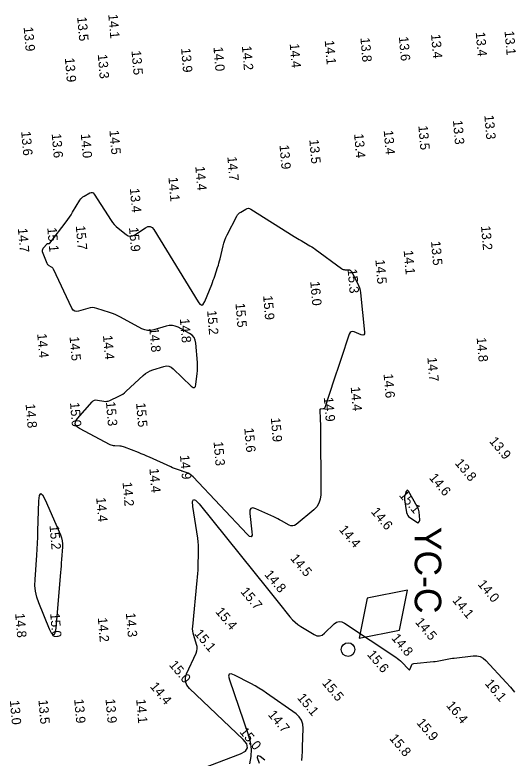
# Model space of a CAD drawing. Extents: x 988130 to 1132882, y 654656 to 841453.
# Drawn here: x 1101312.3 to 1101574.5, y 687754.5 to 688147.1 of the extents above; entities that cross this region are included whole.
import ezdxf

# ---------------------------------------------------------------- set-up
doc = ezdxf.new("R2010")
doc.units = 0
for name, color, linetype in [('V-CHAN-NAID', 7, 'Continuous'), ('V-TOPO-MAJR', 7, 'Continuous'), ('V-TOPO-SOUN', 7, 'Continuous')]:
    doc.layers.add(name, color=color, linetype=linetype)

msp = doc.modelspace()

# ---------------------------------------------------------------- linework, layer by layer
at = {"layer": 'V-CHAN-NAID'}
msp.add_lwpolyline([(1101494.3, 687817.8), (1101515.51, 687822.04), (1101519.76, 687843.26), (1101498.54, 687839.01)], close=True, dxfattribs=at)
msp.add_lwpolyline([(1101494.3, 687817.8), (1101515.51, 687822.04), (1101519.76, 687843.26), (1101498.54, 687839.01)], close=True, dxfattribs=at)
msp.add_circle((1101488.36, 687811.86), 3.6, dxfattribs=at)
msp.add_circle((1101488.36, 687811.86), 3.6, dxfattribs=at)
at = {"layer": 'V-TOPO-MAJR'}
for points in [[(1101489.55, 688012.21), (1101489.88, 688011.94), (1101490.14, 688011.56), (1101493.4, 688005.35), (1101493.96, 688004.15), (1101494.4, 688002.92), (1101494.72, 688001.65), (1101494.92, 688000.34), (1101497.07, 687979.46), (1101497.05, 687978.62), (1101496.76, 687978.13), (1101496.2, 687977.98), (1101495.38, 687978.18), (1101491.59, 687979.67), (1101490.71, 687979.88), (1101490, 687979.75), (1101489.44, 687979.28), (1101489.04, 687978.48), (1101484.5, 687964.99), (1101483.63, 687962.42), (1101482.77, 687959.84), (1101481.92, 687957.27), (1101481.07, 687954.69), (1101476.09, 687939.59), (1101475.96, 687939.32), (1101475.78, 687939.13), (1101475.54, 687939), (1101475.25, 687938.94), (1101473.97, 687938.84), (1101473.7, 687938.78), (1101473.5, 687938.64), (1101473.4, 687938.43), (1101473.38, 687938.15), (1101473.64, 687933.95), (1101473.69, 687933.14), (1101473.72, 687932.34), (1101473.74, 687931.53), (1101473.75, 687930.72), (1101473.91, 687893.52), (1101473.69, 687891.23), (1101473, 687889.16), (1101471.85, 687887.31), (1101470.24, 687885.68), (1101460.96, 687877.98), (1101460.06, 687877.42), (1101459.14, 687877.17), (1101458.18, 687877.25), (1101457.2, 687877.65), (1101453.21, 687879.91), (1101452.21, 687880.46), (1101451.19, 687880.99), (1101450.17, 687881.49), (1101449.13, 687881.97), (1101439.7, 687886.15), (1101438.05, 687886.64), (1101436.95, 687886.39), (1101436.4, 687885.41), (1101436.39, 687883.69), (1101437.6, 687874.06), (1101437.66, 687872.26), (1101437.24, 687871.45), (1101436.35, 687871.65), (1101435, 687872.83), (1101406.5, 687903.06), (1101405.72, 687903.8), (1101404.86, 687904.43), (1101403.93, 687904.95), (1101402.92, 687905.35), (1101398.77, 687906.76), (1101397.74, 687907.12), (1101396.71, 687907.51), (1101395.7, 687907.92), (1101394.7, 687908.36), (1101383.38, 687913.46), (1101381.97, 687914.08), (1101380.56, 687914.69), (1101379.13, 687915.29), (1101377.71, 687915.87), (1101370.33, 687918.82), (1101369.71, 687919.03), (1101369.09, 687919.19), (1101368.45, 687919.3), (1101367.8, 687919.34), (1101365.17, 687919.43), (1101364.52, 687919.48), (1101363.89, 687919.61), (1101363.28, 687919.81), (1101362.69, 687920.08), (1101346.39, 687928.61), (1101344.85, 687929.72), (1101344.17, 687930.99), (1101344.35, 687932.41), (1101345.4, 687933.99), (1101353.12, 687942.69), (1101353.71, 687943.23), (1101354.38, 687943.57), (1101355.12, 687943.71), (1101355.92, 687943.65), (1101359.26, 687943.04), (1101360.09, 687942.95), (1101360.9, 687942.99), (1101361.7, 687943.15), (1101362.48, 687943.45), (1101367.3, 687945.69), (1101368.34, 687946.22), (1101369.32, 687946.82), (1101370.25, 687947.51), (1101371.14, 687948.26), (1101380.17, 687956.68), (1101381.31, 687957.63), (1101382.54, 687958.44), (1101383.85, 687959.1), (1101385.25, 687959.62), (1101391.01, 687961.39), (1101392.4, 687961.64), (1101393.71, 687961.53), (1101394.92, 687961.04), (1101396.05, 687960.18), (1101405.53, 687951.02), (1101406.47, 687950.32), (1101407.19, 687950.23), (1101407.69, 687950.75), (1101407.97, 687951.88), (1101408.66, 687957.65), (1101408.8, 687959.09), (1101408.86, 687960.54), (1101408.86, 687961.98), (1101408.78, 687963.43), (1101407.96, 687973.69), (1101407.65, 687975.3), (1101407, 687976.68), (1101406.01, 687977.84), (1101404.67, 687978.78), (1101398.63, 687982.09), (1101397.1, 687982.75), (1101395.54, 687983.08), (1101393.94, 687983.07), (1101392.31, 687982.73), (1101385.71, 687980.71), (1101384.08, 687980.37), (1101382.48, 687980.36), (1101380.92, 687980.68), (1101379.38, 687981.34), (1101368.19, 687987.4), (1101366.77, 687988.13), (1101365.33, 687988.79), (1101363.86, 687989.38), (1101362.35, 687989.9), (1101355.66, 687992.06), (1101354.46, 687992.35), (1101353.25, 687992.45), (1101352.05, 687992.37), (1101350.84, 687992.09), (1101346.01, 687990.62), (1101344.89, 687990.44), (1101343.93, 687990.63), (1101343.14, 687991.21), (1101342.51, 687992.16), (1101332.77, 688012.7), (1101332.58, 688013.03), (1101332.34, 688013.33), (1101332.07, 688013.59), (1101331.75, 688013.8), (1101330.39, 688014.6), (1101330.07, 688014.82), (1101329.81, 688015.08), (1101329.59, 688015.38), (1101329.42, 688015.72), (1101327, 688021.86), (1101326.86, 688022.38), (1101326.87, 688022.87), (1101327.02, 688023.34), (1101327.32, 688023.79), (1101329.37, 688026.18), (1101329.47, 688026.27), (1101329.57, 688026.33), (1101329.69, 688026.36), (1101329.82, 688026.36), (1101330.36, 688026.32), (1101330.48, 688026.33), (1101330.6, 688026.36), (1101330.7, 688026.42), (1101330.79, 688026.51), (1101339.44, 688037.81), (1101340.34, 688039.03), (1101341.21, 688040.27), (1101342.04, 688041.53), (1101342.84, 688042.82), (1101346.66, 688049.18), (1101347.13, 688049.86), (1101347.67, 688050.46), (1101348.29, 688050.99), (1101348.98, 688051.43), (1101351.9, 688053.07), (1101352.6, 688053.34), (1101353.22, 688053.33), (1101353.78, 688053.04), (1101354.26, 688052.48), (1101363.18, 688038.54), (1101363.97, 688037.41), (1101364.84, 688036.37), (1101365.8, 688035.4), (1101366.84, 688034.5), (1101371.16, 688031.08), (1101372.25, 688030.43), (1101373.36, 688030.17), (1101374.49, 688030.33), (1101375.63, 688030.88), (1101381.37, 688034.65), (1101382.64, 688035.25), (1101383.79, 688035.29), (1101384.82, 688034.76), (1101385.72, 688033.68), (1101409.09, 687995.48), (1101410.09, 687994.22), (1101411.03, 687993.84), (1101411.9, 687994.36), (1101412.69, 687995.77), (1101416.32, 688004.68), (1101416.76, 688005.79), (1101417.19, 688006.91), (1101417.59, 688008.04), (1101417.98, 688009.17), (1101419.48, 688013.71), (1101419.85, 688014.85), (1101420.18, 688016), (1101420.49, 688017.15), (1101420.77, 688018.31), (1101422.31, 688025.06), (1101422.7, 688026.56), (1101423.19, 688028.02), (1101423.77, 688029.45), (1101424.44, 688030.84), (1101429.61, 688040.79), (1101430.01, 688041.45), (1101430.49, 688042.03), (1101431.04, 688042.53), (1101431.68, 688042.96), (1101434.37, 688044.54), (1101435.04, 688044.83), (1101435.71, 688044.92), (1101436.38, 688044.81), (1101437.04, 688044.49), (1101459.83, 688030.11), (1101460.75, 688029.53), (1101461.68, 688028.96), (1101462.61, 688028.41), (1101463.55, 688027.86), (1101467.32, 688025.7), (1101468.26, 688025.15), (1101469.18, 688024.57), (1101470.08, 688023.97), (1101470.97, 688023.34), (1101484.98, 688013.12), (1101485.38, 688012.87), (1101485.82, 688012.68), (1101486.27, 688012.57), (1101486.75, 688012.52), (1101488.7, 688012.45), (1101489.16, 688012.39)], [(1101489.55, 688012.21), (1101489.88, 688011.94), (1101490.14, 688011.56), (1101493.4, 688005.35), (1101493.96, 688004.15), (1101494.4, 688002.92), (1101494.72, 688001.65), (1101494.92, 688000.34), (1101497.07, 687979.46), (1101497.05, 687978.62), (1101496.76, 687978.13), (1101496.2, 687977.98), (1101495.38, 687978.18), (1101491.59, 687979.67), (1101490.71, 687979.88), (1101490, 687979.75), (1101489.44, 687979.28), (1101489.04, 687978.48), (1101484.5, 687964.99), (1101483.63, 687962.42), (1101482.77, 687959.84), (1101481.92, 687957.27), (1101481.07, 687954.69), (1101476.09, 687939.59), (1101475.96, 687939.32), (1101475.78, 687939.13), (1101475.54, 687939), (1101475.25, 687938.94), (1101473.97, 687938.84), (1101473.7, 687938.78), (1101473.5, 687938.64), (1101473.4, 687938.43), (1101473.38, 687938.15), (1101473.64, 687933.95), (1101473.69, 687933.14), (1101473.72, 687932.34), (1101473.74, 687931.53), (1101473.75, 687930.72), (1101473.91, 687893.52), (1101473.69, 687891.23), (1101473, 687889.16), (1101471.85, 687887.31), (1101470.24, 687885.68), (1101460.96, 687877.98), (1101460.06, 687877.42), (1101459.14, 687877.17), (1101458.18, 687877.25), (1101457.2, 687877.65), (1101453.21, 687879.91), (1101452.21, 687880.46), (1101451.19, 687880.99), (1101450.17, 687881.49), (1101449.13, 687881.97), (1101439.7, 687886.15), (1101438.05, 687886.64), (1101436.95, 687886.39), (1101436.4, 687885.41), (1101436.39, 687883.69), (1101437.6, 687874.06), (1101437.66, 687872.26), (1101437.24, 687871.45), (1101436.35, 687871.65), (1101435, 687872.83), (1101406.5, 687903.06), (1101405.72, 687903.8), (1101404.86, 687904.43), (1101403.93, 687904.95), (1101402.92, 687905.35), (1101398.77, 687906.76), (1101397.74, 687907.12), (1101396.71, 687907.51), (1101395.7, 687907.92), (1101394.7, 687908.36), (1101383.38, 687913.46), (1101381.97, 687914.08), (1101380.56, 687914.69), (1101379.13, 687915.29), (1101377.71, 687915.87), (1101370.33, 687918.82), (1101369.71, 687919.03), (1101369.09, 687919.19), (1101368.45, 687919.3), (1101367.8, 687919.34), (1101365.17, 687919.43), (1101364.52, 687919.48), (1101363.89, 687919.61), (1101363.28, 687919.81), (1101362.69, 687920.08), (1101346.39, 687928.61), (1101344.85, 687929.72), (1101344.17, 687930.99), (1101344.35, 687932.41), (1101345.4, 687933.99), (1101353.12, 687942.69), (1101353.71, 687943.23), (1101354.38, 687943.57), (1101355.12, 687943.71), (1101355.92, 687943.65), (1101359.26, 687943.04), (1101360.09, 687942.95), (1101360.9, 687942.99), (1101361.7, 687943.15), (1101362.48, 687943.45), (1101367.3, 687945.69), (1101368.34, 687946.22), (1101369.32, 687946.82), (1101370.25, 687947.51), (1101371.14, 687948.26), (1101380.17, 687956.68), (1101381.31, 687957.63), (1101382.54, 687958.44), (1101383.85, 687959.1), (1101385.25, 687959.62), (1101391.01, 687961.39), (1101392.4, 687961.64), (1101393.71, 687961.53), (1101394.92, 687961.04), (1101396.05, 687960.18), (1101405.53, 687951.02), (1101406.47, 687950.32), (1101407.19, 687950.23), (1101407.69, 687950.75), (1101407.97, 687951.88), (1101408.66, 687957.65), (1101408.8, 687959.09), (1101408.86, 687960.54), (1101408.86, 687961.98), (1101408.78, 687963.43), (1101407.96, 687973.69), (1101407.65, 687975.3), (1101407, 687976.68), (1101406.01, 687977.84), (1101404.67, 687978.78), (1101398.63, 687982.09), (1101397.1, 687982.75), (1101395.54, 687983.08), (1101393.94, 687983.07), (1101392.31, 687982.73), (1101385.71, 687980.71), (1101384.08, 687980.37), (1101382.48, 687980.36), (1101380.92, 687980.68), (1101379.38, 687981.34), (1101368.19, 687987.4), (1101366.77, 687988.13), (1101365.33, 687988.79), (1101363.86, 687989.38), (1101362.35, 687989.9), (1101355.66, 687992.06), (1101354.46, 687992.35), (1101353.25, 687992.45), (1101352.05, 687992.37), (1101350.84, 687992.09), (1101346.01, 687990.62), (1101344.89, 687990.44), (1101343.93, 687990.63), (1101343.14, 687991.21), (1101342.51, 687992.16), (1101332.77, 688012.7), (1101332.58, 688013.03), (1101332.34, 688013.33), (1101332.07, 688013.59), (1101331.75, 688013.8), (1101330.39, 688014.6), (1101330.07, 688014.82), (1101329.81, 688015.08), (1101329.59, 688015.38), (1101329.42, 688015.72), (1101327, 688021.86), (1101326.86, 688022.38), (1101326.87, 688022.87), (1101327.02, 688023.34), (1101327.32, 688023.79), (1101329.37, 688026.18), (1101329.47, 688026.27), (1101329.57, 688026.33), (1101329.69, 688026.36), (1101329.82, 688026.36), (1101330.36, 688026.32), (1101330.48, 688026.33), (1101330.6, 688026.36), (1101330.7, 688026.42), (1101330.79, 688026.51), (1101339.44, 688037.81), (1101340.34, 688039.03), (1101341.21, 688040.27), (1101342.04, 688041.53), (1101342.84, 688042.82), (1101346.66, 688049.18), (1101347.13, 688049.86), (1101347.67, 688050.46), (1101348.29, 688050.99), (1101348.98, 688051.43), (1101351.9, 688053.07), (1101352.6, 688053.34), (1101353.22, 688053.33), (1101353.78, 688053.04), (1101354.26, 688052.48), (1101363.18, 688038.54), (1101363.97, 688037.41), (1101364.84, 688036.37), (1101365.8, 688035.4), (1101366.84, 688034.5), (1101371.16, 688031.08), (1101372.25, 688030.43), (1101373.36, 688030.17), (1101374.49, 688030.33), (1101375.63, 688030.88), (1101381.37, 688034.65), (1101382.64, 688035.25), (1101383.79, 688035.29), (1101384.82, 688034.76), (1101385.72, 688033.68), (1101409.09, 687995.48), (1101410.09, 687994.22), (1101411.03, 687993.84), (1101411.9, 687994.36), (1101412.69, 687995.77), (1101416.32, 688004.68), (1101416.76, 688005.79), (1101417.19, 688006.91), (1101417.59, 688008.04), (1101417.98, 688009.17), (1101419.48, 688013.71), (1101419.85, 688014.85), (1101420.18, 688016), (1101420.49, 688017.15), (1101420.77, 688018.31), (1101422.31, 688025.06), (1101422.7, 688026.56), (1101423.19, 688028.02), (1101423.77, 688029.45), (1101424.44, 688030.84), (1101429.61, 688040.79), (1101430.01, 688041.45), (1101430.49, 688042.03), (1101431.04, 688042.53), (1101431.68, 688042.96), (1101434.37, 688044.54), (1101435.04, 688044.83), (1101435.71, 688044.92), (1101436.38, 688044.81), (1101437.04, 688044.49), (1101459.83, 688030.11), (1101460.75, 688029.53), (1101461.68, 688028.96), (1101462.61, 688028.41), (1101463.55, 688027.86), (1101467.32, 688025.7), (1101468.26, 688025.15), (1101469.18, 688024.57), (1101470.08, 688023.97), (1101470.97, 688023.34), (1101484.98, 688013.12), (1101485.38, 688012.87), (1101485.82, 688012.68), (1101486.27, 688012.57), (1101486.75, 688012.52), (1101488.7, 688012.45), (1101489.16, 688012.39)], [(1101519.73, 687896.05), (1101519.49, 687895.89), (1101519.27, 687895.46), (1101518.44, 687893.22), (1101518.27, 687892.65), (1101518.18, 687892.08), (1101518.16, 687891.5), (1101518.22, 687890.91), (1101519.32, 687884.24), (1101519.54, 687883.43), (1101519.89, 687882.72), (1101520.4, 687882.11), (1101521.05, 687881.58), (1101525.05, 687878.95), (1101525.21, 687878.88), (1101525.36, 687878.87), (1101525.5, 687878.93), (1101525.62, 687879.05), (1101526.1, 687879.69), (1101526.21, 687879.85), (1101526.27, 687880.03), (1101526.31, 687880.21), (1101526.31, 687880.41), (1101525.89, 687884.6), (1101525.78, 687885.35), (1101525.59, 687886.08), (1101525.32, 687886.78), (1101524.97, 687887.46), (1101520.28, 687895.55), (1101520, 687895.93)], [(1101324.27, 687868.08), (1101324.42, 687871.28), (1101324.54, 687874.48), (1101325.07, 687890.41), (1101325.37, 687893.24), (1101326.01, 687894.29), (1101326.99, 687893.55), (1101328.31, 687891.03), (1101336.45, 687872.51), (1101337.02, 687870.95), (1101337.4, 687869.36), (1101337.57, 687867.73), (1101337.54, 687866.07), (1101337.01, 687859.35), (1101336.87, 687857.67), (1101336.74, 687855.99), (1101336.6, 687854.32), (1101336.46, 687852.64), (1101333.95, 687823.18), (1101333.52, 687820.49), (1101332.83, 687819.5), (1101331.87, 687820.23), (1101330.65, 687822.68), (1101324.98, 687836.58), (1101323.95, 687839.58), (1101323.28, 687842.63), (1101322.96, 687845.74), (1101323, 687848.91), (1101323.89, 687861.69), (1101324.09, 687864.89)]]:
    msp.add_lwpolyline(points, close=True, dxfattribs=at)
for points in [[(1101411.72, 687749.26), (1101431.46, 687756.76), (1101434.1, 687758.2), (1101435.24, 687759.95), (1101434.86, 687761.99), (1101432.99, 687764.34), (1101404.55, 687791.36), (1101403.14, 687793.08), (1101402.43, 687794.95), (1101402.4, 687796.94), (1101403.06, 687799.07), (1101408.05, 687810), (1101408.45, 687811.12), (1101408.63, 687812.26), (1101408.58, 687813.41), (1101408.32, 687814.58), (1101406.81, 687819.26), (1101406.49, 687820.44), (1101406.3, 687821.63), (1101406.24, 687822.84), (1101406.3, 687824.05), (1101408.71, 687848.27), (1101408.88, 687850.13), (1101409.02, 687852), (1101409.12, 687853.88), (1101409.19, 687855.75), (1101409.41, 687863.25), (1101409.42, 687865.12), (1101409.34, 687866.99), (1101409.19, 687868.85), (1101408.94, 687870.71), (1101406.38, 687887.38), (1101406.2, 687890.02), (1101406.68, 687891.14), (1101407.83, 687890.74), (1101409.65, 687888.82), (1101445.73, 687843.99), (1101447.17, 687842.2), (1101448.61, 687840.41), (1101450.05, 687838.61), (1101451.49, 687836.82), (1101457.69, 687829.09), (1101458.96, 687827.63), (1101460.35, 687826.3), (1101461.85, 687825.11), (1101463.46, 687824.04), (1101470.48, 687819.83), (1101471.95, 687819.19), (1101473.37, 687819.09), (1101474.72, 687819.51), (1101476.01, 687820.47), (1101481.04, 687825.38), (1101482.33, 687826.34), (1101483.66, 687826.74), (1101485.05, 687826.59), (1101486.49, 687825.89), (1101513.61, 687807.81), (1101514.45, 687807.22), (1101515.24, 687806.59), (1101516, 687805.91), (1101516.72, 687805.19), (1101520.27, 687801.43), (1101520.58, 687801.18), (1101520.84, 687801.13), (1101521.06, 687801.29), (1101521.24, 687801.65), (1101521.84, 687803.49), (1101522.03, 687803.9), (1101522.31, 687804.2), (1101522.67, 687804.41), (1101523.11, 687804.5), (1101533.57, 687805.52), (1101534.48, 687805.62), (1101535.39, 687805.74), (1101536.29, 687805.89), (1101537.19, 687806.06), (1101540.78, 687806.78), (1101541.68, 687806.96), (1101542.59, 687807.11), (1101543.49, 687807.24), (1101544.4, 687807.36), (1101554.47, 687808.56), (1101556.37, 687808.58), (1101558.12, 687808.18), (1101559.71, 687807.35), (1101561.14, 687806.1), (1101571.99, 687794.42), (1101574.21, 687791.94), (1101576.32, 687789.39)], [(1101463.98, 687753.18), (1101464.12, 687755.61), (1101464.24, 687758.05), (1101464.34, 687760.48), (1101464.68, 687770.23), (1101464.51, 687772.53), (1101463.82, 687774.58), (1101462.61, 687776.38), (1101460.88, 687777.91), (1101445.35, 687788.9), (1101443.35, 687790.27), (1101441.3, 687791.55), (1101439.21, 687792.77), (1101437.07, 687793.9), (1101428.42, 687798.3), (1101426.63, 687798.97), (1101425.58, 687798.8), (1101425.26, 687797.78), (1101425.68, 687795.91), (1101435.64, 687766.93), (1101436.66, 687763.12), (1101437.1, 687759.29), (1101436.97, 687755.44), (1101436.27, 687751.56)], [(1101441.67, 687751.63), (1101440.56, 687754.64), (1101440.64, 687755.96), (1101441.91, 687755.59), (1101444.37, 687753.53)]]:
    msp.add_lwpolyline(points, dxfattribs=at)

# ---------------------------------------------------------------- texts
at = {"layer": 'V-CHAN-NAID'}
msp.add_text('YC-C', height=14, rotation=270, dxfattribs=at).set_placement((1101523.62, 687876.68))
msp.add_text('YC-C', height=14, rotation=270, dxfattribs=at).set_placement((1101523.62, 687876.68))
at = {"layer": 'V-TOPO-SOUN'}
for s, rotation, p in [('13.5 ', 275, (1101345.22, 688145.99)), ('14.1 ', 275, (1101361.66, 688147.38)), ('13.9 ', 275, (1101316.95, 688140.59)), ('13.4 ', 275, (1101532.19, 688136.83)), ('13.4 ', 275, (1101555.81, 688137.92)), ('13.1 ', 275, (1101571.05, 688138.55)), ('14.4 ', 275, (1101457.52, 688131.83)), ('14.1 ', 275, (1101476.03, 688133.54)), ('13.8 ', 275, (1101494.89, 688134.95)), ('13.6 ', 275, (1101515.22, 688135.5)), ('13.5 ', 275, (1101373.93, 688128.11)), ('13.9 ', 275, (1101400.12, 688129.43)), ('14.0 ', 275, (1101417.23, 688130.1)), ('14.2 ', 275, (1101432.26, 688130.62)), ('13.9 ', 275, (1101338.71, 688124.3)), ('13.3 ', 275, (1101356.11, 688126.16)), ('13.3 ', 275, (1101560.37, 688094.06)), ('13.3 ', 275, (1101543.78, 688091.36)), ('13.6 ', 275, (1101315.65, 688085.5)), ('14.5 ', 275, (1101362.27, 688086.06)), ('13.4 ', 275, (1101507.2, 688086.01)), ('13.5 ', 275, (1101525.51, 688088.5)), ('13.6 ', 275, (1101331.78, 688084.26)), ('14.0 ', 275, (1101347.13, 688084.21)), ('13.5 ', 275, (1101467.89, 688081.21)), ('13.4 ', 275, (1101491.55, 688084.22)), ('13.9 ', 275, (1101452.13, 688078.3)), ('14.7 ', 275, (1101424.59, 688072.15)), ('14.4 ', 275, (1101407.66, 688067.02)), ('14.1 ', 275, (1101393.44, 688061.3)), ('13.4 ', 275, (1101373.08, 688055.41)), ('14.7 ', 275, (1101313.88, 688034.33)), ('15.1 ', 275, (1101329.45, 688034.61)), ('15.7 ', 275, (1101344.5, 688035.63)), ('15.9 ', 275, (1101372.61, 688034.76)), ('13.2 ', 275, (1101558.6, 688035.58)), ('13.5 ', 275, (1101532.2, 688027.51)), ('14.1 ', 275, (1101517.75, 688022.62)), ('14.5 ', 275, (1101502.8, 688017.7)), ('15.3 ', 275, (1101488.12, 688012.76)), ('16.0 ', 275, (1101468.39, 688006.26)), ('15.9 ', 275, (1101443.47, 687998.74)), ('15.5 ', 275, (1101428.85, 687994.75)), ('15.2 ', 275, (1101413.87, 687990.88)), ('14.8 ', 275, (1101399.47, 687986.61)), ('14.8 ', 275, (1101383.35, 687981.66)), ('14.4 ', 275, (1101324.12, 687978.63)), ('14.5 ', 275, (1101341.2, 687977.12)), ('14.4 ', 275, (1101358.87, 687977.73)), ('14.8 ', 275, (1101556.31, 687976.57)), ('14.7 ', 275, (1101530.26, 687966.14)), ('14.6 ', 275, (1101507.12, 687957.44)), ('14.4 ', 275, (1101489.76, 687950.59)), ('14.9 ', 275, (1101475.52, 687945.04)), ('14.8 ', 275, (1101317.98, 687941.57)), ('15.0 ', 275, (1101341.43, 687942.29)), ('15.3 ', 275, (1101360.44, 687942.66)), ('15.5 ', 275, (1101376.35, 687942.09)), ('15.9 ', 275, (1101447.54, 687934.21)), ('15.6 ', 275, (1101433.54, 687928.78)), ('13.9 ', 310, (1101562.72, 687921.75)), ('15.3 ', 275, (1101417.3, 687921.64)), ('14.9 ', 275, (1101399.54, 687914.48)), ('13.8 ', 310, (1101544.54, 687910.18)), ('14.4 ', 275, (1101383.39, 687907.45)), ('14.6 ', 310, (1101530.92, 687902.47)), ('14.2 ', 275, (1101369.21, 687900.23)), ('15.1 ', 310, (1101515.07, 687893.22)), ('14.4 ', 275, (1101355.27, 687892.07)), ('14.6 ', 310, (1101500.24, 687884.49)), ('15.2 ', 275, (1101330.62, 687877.37)), ('14.4 ', 310, (1101483.34, 687875.1)), ('14.5 ', 310, (1101457.6, 687859.87)), ('14.8 ', 310, (1101443.92, 687851.36)), ('14.0 ', 310, (1101556.59, 687846.24)), ('15.7 ', 310, (1101431.3, 687842.31)), ('14.1 ', 310, (1101543.18, 687837.75)), ('15.4 ', 310, (1101418.03, 687831.72)), ('14.8 ', 275, (1101312.46, 687830.9)), ('15.0 ', 275, (1101330.95, 687830.97)), ('14.3 ', 275, (1101370.95, 687831.17)), ('14.2 ', 275, (1101356.13, 687828.59)), ('14.5 ', 310, (1101523.57, 687826.22)), ('15.1 ', 310, (1101406.87, 687820.13)), ('14.8 ', 310, (1101511.02, 687817.8)), ('15.6 ', 310, (1101498.21, 687809.07)), ('15.0 ', 310, (1101393.55, 687803.62)), ('14.4 ', 310, (1101383.47, 687792.2)), ('15.5 ', 310, (1101474.38, 687794.05)), ('16.1 ', 310, (1101560.4, 687793.79)), ('15.1 ', 310, (1101461.21, 687786.27)), ('13.0 ', 275, (1101309.67, 687784.93)), ('13.5 ', 275, (1101324.75, 687785.24)), ('13.9 ', 275, (1101343.65, 687785.62)), ('13.9 ', 275, (1101360.21, 687785.7)), ('14.1 ', 275, (1101376.4, 687785.61)), ('16.4 ', 310, (1101540, 687782.2)), ('14.7 ', 310, (1101445.79, 687777.34)), ('15.9 ', 310, (1101524.3, 687773.05)), ('15.0 ', 310, (1101430.75, 687768.28)), ('15.8 ', 310, (1101509.95, 687764.81))]:
    msp.add_text(s, height=5, rotation=rotation, dxfattribs=at).set_placement(p)

doc.saveas('drawing.dxf')
